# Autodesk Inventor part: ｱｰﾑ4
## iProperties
Created: 2008-02
Part Number: ｱｰﾑ4
Document SubType Name: Modeling
Designer: y-shimazaki
Density: 1 g/cm^3
Author: y-shimazaki
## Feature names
1. 押し出し1 [Extrusion]
2. 押し出し2 [Extrusion]
3. 押し出し3 [Extrusion]
4. 押し出し4 [Extrusion]
